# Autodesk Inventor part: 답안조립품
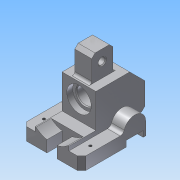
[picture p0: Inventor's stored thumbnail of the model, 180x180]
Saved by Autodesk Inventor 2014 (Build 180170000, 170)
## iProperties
Created: 2016-11
Part Number: 답안조립품
Material: 알루미늄 6061
Document SubType Name: Modeling
Designer: net
Density: 2.71 g/cm^3
Appearance: 알루미늄 - 평지
Mass: 459.661 g
Surface Area: 317.207 cm^2
Volume: 169.617 cm^3
Author: net
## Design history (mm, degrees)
sketch "스케치1"
  geometry: L1 (-35, 38)-(35, 38); L2 (35, 38)-(35, -38); L3 (35, -38)-(-35, -38); L4 (-35, -38)-(-35, 38); 3 further points
  constraints: 8 end point, 2 midpoint, 2 parallel, 1 horizontal, 1 horizontal alignment, 1 perpendicular, 1 vertical alignment
  dimensions: "d0" = 70 distance of L2.end L3.end; "d1" = 76 distance of L3.end L1.start
extrude "돌출1" new body sketch "스케치1" distance "d2" = 15; taper "d3" = 0 deg
sketch "스케치2"
  geometry: L1 (0, 0)-(0, 76) reference; L2 (0, 76)-(15, 76) reference; L3 (0, 73)-(7, 73); L4 (7, 73)-(7, 53); L5 (7, 53)-(0, 53); L6 (0, 53)-(0, 73); 1 further point
  constraints: 8 end point, 2 parallel, 1 horizontal, 1 perpendicular, 1 point on line
  dimensions: "d4" = 3 distance between parallel lines of L3 L2; "d5" = 7 distance of L3.start L3.end; "d6" = 20 distance between parallel lines of L5 L3
extrude "돌출2" cut sketch "스케치2" stored distance "d7" = 15; taper "d8" = 0 deg
sketch "스케치5"
  geometry: L1 (-15, 73)-(-8, 73) reference; L2 (-8, 73)-(-8, 53) reference; L3 (-8, 53)-(-15, 53) reference; L4 (-15, 0)-(-15, 53) reference; L5 (-15, 0)-(0, 0) reference; L6 (0, 76)-(0, 0) reference; L7 (-15, 76)-(0, 76) reference; L8 (-15, 73)-(-15, 76) reference; A1 r 13 centre (0, 63) between (0, 50) and (0, 76); 1 further point
  constraints: 3 point on line, 2 point on circle, 1 centre point
  dimensions: "d15" = 13 distance from line of A1.centre L7; "d16" = 26 diameter of A1
extrude "돌출4" join sketch "스케치5" distance "d17" = 70; taper "d18" = 0 deg
sketch "스케치6"
  geometry: L1 (-35, -38)-(35, -38) reference; L2 (-20, -38)-(20, -38); L3 (20, -38)-(20, 52); L4 (20, 52)-(-20, 52); L5 (-20, 52)-(-20, -38); 2 further points
  constraints: 8 end point, 2 parallel, 1 horizontal, 1 midpoint, 1 perpendicular, 1 point on line, 1 vertical alignment
  dimensions: "d19" = 40 distance of L3.end L4.end; "d20" = 90 distance of L2.end L3.end
extrude "돌출5" join sketch "스케치6" distance "d21" = 5; taper "d22" = 0 deg
sketch "스케치7"
  geometry: L1 (20, -38)-(20, 13) reference; L2 (20, 37)-(-20, 37) reference; L3 (20, 37)-(20, 52) reference; L4 (20, 52)-(-20, 52) reference; L5 (-20, 52)-(-20, 37) reference; L6 (-20, 52)-(20, 52); L7 (20, 52)-(20, -6); L8 (20, -6)-(-20, -6); L9 (-20, -6)-(-20, 52); 1 further point
  constraints: 8 end point, 2 parallel, 1 horizontal, 1 perpendicular, 1 point on line
  dimensions: "d23" = 58 distance between parallel lines of L8 L6
extrude "돌출6" join sketch "스케치7" distance "d24" = 40; taper "d25" = 0 deg
sketch "스케치8"
  geometry: L1 (-20, 52)-(20, 52); L2 (20, 52)-(20, 38); L3 (20, 38)-(-20, 38); L4 (-20, 38)-(-20, 52); 1 further point
  constraints: 8 end point, 2 parallel, 1 horizontal, 1 perpendicular
extrude "돌출7" join sketch "스케치8" distance "d26" = 3; taper "d27" = 0 deg
sketch "스케치13"
  geometry: L1 (-20, -6)-(20, -6) reference; L2 (-10, -1)-(10, -1); L3 (10, -1)-(10, 24); L4 (10, 24)-(-10, 24); L5 (-10, 24)-(-10, -1); 2 further points
  constraints: 8 end point, 2 parallel, 1 horizontal, 1 midpoint, 1 perpendicular, 1 vertical alignment
  dimensions: "d38" = 20 distance of L2.start L2.end; "d39" = 5 distance between parallel lines of L2 L1; "d40" = 25 distance of L4.end L2.start
extrude "돌출10" join sketch "스케치13" distance "d41" = 30; taper "d42" = 0 deg
sketch "스케치15"
  geometry: L1 (45, 90)-(45, 32) reference; L2 (-3, 90)-(45, 90) reference; L3 (45, 90)-(45, 72); L4 (45, 72)-(27, 90); L5 (27, 90)-(45, 90); 1 further point
  constraints: 6 end point, 2 point on line, 1 collinear
  dimensions: "d43" = 18 distance of L1.start L3.end; "d44" = 45 deg angle of L3 L4
extrude "돌출11" cut sketch "스케치15" stored distance "d45" = 23; taper "d46" = 0 deg
sketch "스케치16"
  geometry: L1 (55, -20)-(-15, -20) reference; 3 further points
  constraints: 1 midpoint, 1 vertical alignment
  dimensions: "d47" = 42 distance from line of point (20, 22) L1
hole "구멍1" sketch "스케치16" at (20, 22) diameter "d48" = 20; stored, may be unused: countersink angle "d52" = 90 deg, drill point angle "d54" = 0 deg; dims "d49" = 6, "d50" = 29, "d51" = 7, "d53" = 8
sketch "스케치17"
  geometry: L1 (0, 25)-(30, 25) reference; L2 (-3.5, -5)-(-32.5, -5) reference; L3 (-32.5, 2)-(-3.5, 2) reference; L4 (-60, -37)-(-60, 16) reference; 2 further points
  dimensions: "d55" = 77 distance from line of L4 point (17, 12.5); "d56" = 12.5 distance from line of point (17, 12.5) L1
hole "구멍2" sketch "스케치17" at (17, 12.5) diameter "d57" = 8; stored, may be unused: countersink angle "d61" = 90 deg, drill point angle "d63" = 0 deg; dims "d58" = 6, "d59" = 29, "d60" = 7, "d62" = 8
chamfer "모따기1" distance "d64" = 4; stored, may be unused: second distance "d65" = 2, angle "d66" = 45 deg
sketch "스케치18"
  geometry: C1 r 10 at (35, 42) reference; C2 r 29 at (35, 42); 1 further point
  constraints: 1 centre point, 1 coincident
  dimensions: "d67" = 58 diameter of C2
extrude "돌출12" cut sketch "스케치18" distance "d68" = 18; taper "d69" = 0 deg
sketch "스케치19"
  geometry: L1 (70, 0)-(0, 0) reference; L2 (29, 0)-(41, 0); L3 (41, 0)-(41, 20); L4 (41, 20)-(29, 20); L5 (29, 20)-(29, 0); A1 r 29 centre (35, 42) between (16.106, 20) and (53.894, 20) reference; 2 further points
  constraints: 8 end point, 2 parallel, 1 horizontal, 1 midpoint, 1 perpendicular, 1 point on line, 1 vertical alignment
  dimensions: "d70" = 12 distance of L3.end L4.end; "d71" = 20 distance between parallel lines of L4 L1
extrude "돌출13" cut sketch "스케치19" distance "d72" = 18; taper "d73" = 0 deg
chamfer "모따기2" distance "d74" = 5; stored, may be unused: second distance "d75" = 2, angle "d76" = 45 deg
sketch "스케치20"
  geometry: L1 (-30, -38)-(-20, -38) reference; L2 (-35, 12)-(-35, -33) reference; L3 (27.5, -20)-(-27.5, -20); L4 (-18.894, -20)-(18.894, -20) reference; 3 further points
  constraints: 2 end point, 2 midpoint, 1 coincident, 1 perpendicular
  dimensions: "d77" = 55 distance of L3.start L3.end; "d78" = 18 distance from line of L1 L3.end
hole "구멍3" sketch "스케치20" at (27.5, -20), (-27.5, -20) diameter "d79" = 3.242; stored, may be unused: countersink angle "d83" = 90 deg, drill point angle "d85" = 0 deg; dims "d80" = 6, "d81" = 29, "d82" = 7, "d84" = 8
sketch "스케치21"
  geometry: L1 (5, 32)-(45, 32) reference; L2 (45, 72)-(45, 32) reference; 2 further points
  constraints: 1 other
  dimensions: "d86" = 25 distance from line of L1 point (27, 57); "d87" = 18 distance from line of point (27, 57) L2
feature "엠보싱1" sketch "스케치21" dims "d0" = 70, "d1" = 76, "d88" = 0.5, "d89" = 0
chamfer "모따기3" distance "d90" = 1; stored, may be unused: second distance "d91" = 2, angle "d92" = 45 deg
fillet "모깎기1" dims "d93" = 5
fillet "모깎기2" dims "d94" = 3
chamfer "모따기5" distance "d98" = 4; stored, may be unused: second distance "d99" = 2, angle "d100" = 45 deg
node "솔리드1"
node "투영된 루프1"
other parameters: "d12" = 26 (derived)
